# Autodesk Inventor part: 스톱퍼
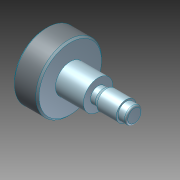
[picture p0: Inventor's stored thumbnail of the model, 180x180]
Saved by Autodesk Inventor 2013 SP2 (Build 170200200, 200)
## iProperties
Created: 2024-07
Part Number: 스톱퍼
Material: Generic
Document SubType Name: Modeling
Designer: 601
Density: 1 g/cm^3
Author: 601
변환 표준: STEP AP214IS
전처리기: Build: 200, Release: 2013 SP2 Update 6 - Date: Thu 07/17/2014
전송 단위: 밀리미터
불확실성: 0.01
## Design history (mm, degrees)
node "스톱퍼1"
node "솔리드1"
node "기준1"
